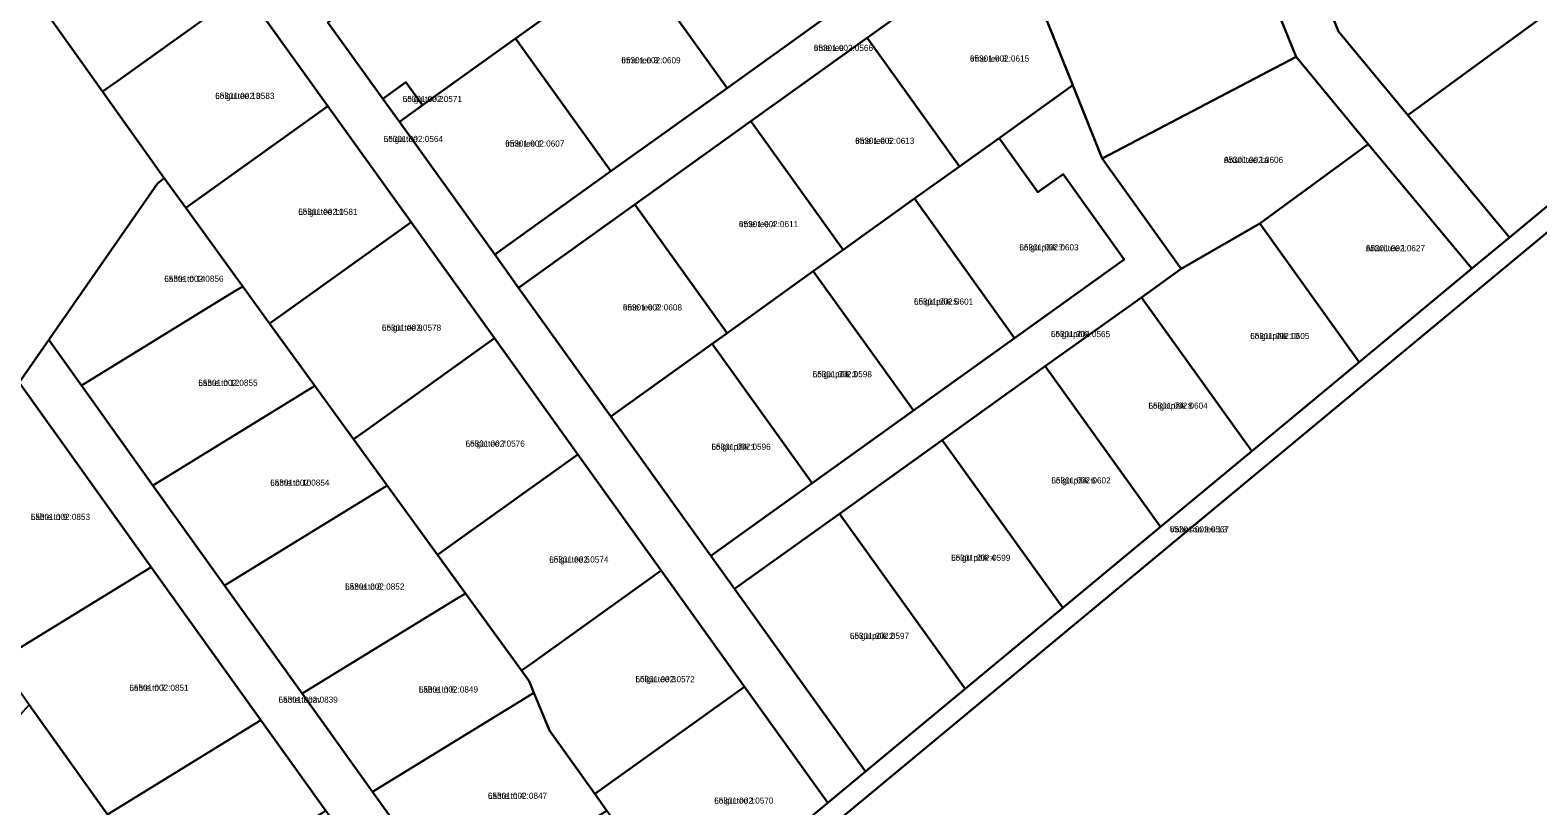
# Model space of a CAD drawing. Extents: x 543236 to 563717, y 6566033 to 6588992.
# Drawn here: x 547510.5 to 547879.6, y 6584286.1 to 6584476.1 of the extents above; entities that cross this region are included whole.
import ezdxf

# ---------------------------------------------------------------- set-up
doc = ezdxf.new("R2010")
doc.units = 0
for name, color, linetype in [('L_AADRESS', 7, 'Continuous'), ('PIIR', 7, 'Continuous'), ('TUNNUS', 7, 'Continuous')]:
    doc.layers.add(name, color=color, linetype=linetype)

msp = doc.modelspace()

# ---------------------------------------------------------------- linework, layer by layer
at = {"layer": 'PIIR'}
for points in [[(547954.94, 6584897.14), (548418, 6584661.07), (548073.21, 6584219.71), (547822.9, 6584045.85), (547791.34, 6584089.91), (547762.23, 6584130.56), (547726.58, 6584180.33), (547703.79, 6584212.15), (547681.42, 6584243.38), (547673.85, 6584253.95), (547904.47, 6584445.32), (547908.07, 6584486.9), (547820.46, 6584606.43), (547748.48, 6584706.18), (547740.64, 6584722.91), (547735.69, 6584759.78), (547742.32, 6584763.93)], [(547796.24, 6584529.04), (547800, 6584519.77), (547750.86, 6584499.7), (547715.36, 6584474.23), (547686.92, 6584453.83), (547658.48, 6584433.43), (547630.04, 6584413.03), (547624.21, 6584421.16), (547652.65, 6584441.56), (547681.09, 6584461.96), (547709.53, 6584482.36), (547737.97, 6584502.76), (547745.99, 6584508.51), (547769.91, 6584518.28)], [(547878.99, 6584526.57), (547902.04, 6584495.12), (547900.01, 6584493.63), (547847.76, 6584455.33), (547830.78, 6584475.79), (547825.95, 6584487.7), (547876.96, 6584525.09)], [(547820.36, 6584469.56), (547772.89, 6584444.67), (547750.86, 6584499.7), (547800, 6584519.77)], [(547542.55, 6584514.42), (547562.95, 6584485.98), (547531.95, 6584463.74), (547528.23, 6584461.08), (547507.95, 6584489.6), (547510.92, 6584491.73)], [(547686.22, 6584514.86), (547709.53, 6584482.36), (547681.09, 6584461.96), (547657.78, 6584494.46)], [(547632.16, 6584513.01), (547649.65, 6584488.63), (547629.34, 6584474.06), (547606.58, 6584457.74), (547602.5, 6584463.43), (547596.82, 6584459.35), (547583.41, 6584478.04)], [(547750.86, 6584499.7), (547765.71, 6584462.62), (547747.69, 6584449.71), (547737.96, 6584442.73), (547715.36, 6584474.23)], [(547657.78, 6584494.46), (547681.09, 6584461.96), (547652.65, 6584441.56), (547629.34, 6584474.06), (547649.65, 6584488.63)], [(547902.04, 6584495.12), (547908.07, 6584486.9), (547905.08, 6584452.32), (547872.61, 6584425.38), (547847.76, 6584455.33), (547900.01, 6584493.63)], [(547562.95, 6584485.98), (547583.35, 6584457.54), (547551.49, 6584434.69), (547548.58, 6584432.6), (547543.32, 6584439.85), (547528.23, 6584461.08), (547531.95, 6584463.74)], [(547629.34, 6584474.06), (547652.65, 6584441.56), (547624.21, 6584421.16), (547600.9, 6584453.66), (547606.58, 6584457.74)], [(547715.36, 6584474.23), (547737.96, 6584442.73), (547726.99, 6584434.86), (547709.52, 6584422.33), (547686.92, 6584453.83)], [(547820.36, 6584469.56), (547838.06, 6584448.23), (547811.47, 6584428.74), (547792.25, 6584417.68), (547772.89, 6584444.67)], [(547602.5, 6584463.43), (547606.58, 6584457.74), (547600.9, 6584453.66), (547596.82, 6584459.35)], [(547765.71, 6584462.62), (547772.89, 6584444.67), (547792.25, 6584417.68), (547782.5, 6584410.68), (547758.97, 6584393.81), (547733.78, 6584375.74), (547708.59, 6584357.67), (547682.95, 6584339.27), (547677.12, 6584347.4), (547701.9, 6584365.18), (547726.69, 6584382.95), (547751.47, 6584400.73), (547778.3, 6584419.98), (547763.33, 6584440.83), (547757.2, 6584436.44), (547747.69, 6584449.71)], [(547583.35, 6584457.54), (547603.75, 6584429.1), (547571.86, 6584406.23), (547569.13, 6584404.27), (547548.58, 6584432.6), (547551.49, 6584434.69)], [(547686.92, 6584453.83), (547709.52, 6584422.33), (547702.21, 6584417.08), (547681.08, 6584401.93), (547658.48, 6584433.43)], [(547905.08, 6584452.32), (547904.47, 6584445.32), (547673.85, 6584253.95), (547670.93, 6584258.03), (547705.74, 6584286.91), (547715, 6584294.59), (547739.35, 6584314.8), (547763.26, 6584334.64), (547787.18, 6584354.49), (547809.52, 6584373.02), (547835.79, 6584394.83), (547863.38, 6584417.72), (547872.61, 6584425.38)], [(547747.69, 6584449.71), (547757.2, 6584436.44), (547763.33, 6584440.83), (547778.3, 6584419.98), (547751.47, 6584400.73), (547726.99, 6584434.86), (547737.96, 6584442.73)], [(547838.06, 6584448.23), (547863.38, 6584417.72), (547835.79, 6584394.83), (547811.47, 6584428.74)], [(547515.08, 6584400.26), (547541.71, 6584438.59), (547543.32, 6584439.85), (547548.58, 6584432.6), (547562.53, 6584413.37), (547560.47, 6584412.11), (547523.04, 6584389.14)], [(547658.48, 6584433.43), (547681.08, 6584401.93), (547677.42, 6584399.3), (547652.64, 6584381.53), (547630.04, 6584413.03)], [(547726.99, 6584434.86), (547751.47, 6584400.73), (547726.69, 6584382.95), (547702.21, 6584417.08), (547709.52, 6584422.33)], [(547603.75, 6584429.1), (547624.15, 6584400.66), (547592.59, 6584378.02), (547589.68, 6584375.94), (547569.13, 6584404.27), (547571.86, 6584406.23)], [(547811.47, 6584428.74), (547835.79, 6584394.83), (547809.52, 6584373.02), (547782.5, 6584410.68), (547792.25, 6584417.68)], [(547702.21, 6584417.08), (547726.69, 6584382.95), (547701.9, 6584365.18), (547677.42, 6584399.3), (547681.08, 6584401.93)], [(547523.04, 6584389.14), (547560.47, 6584412.11), (547562.53, 6584413.37), (547569.13, 6584404.27), (547580.22, 6584388.98), (547578.1, 6584387.68), (547540.57, 6584364.65)], [(547782.5, 6584410.68), (547809.52, 6584373.02), (547787.18, 6584354.49), (547758.97, 6584393.81)], [(547507.82, 6584389.8), (547515.08, 6584400.26), (547523.04, 6584389.14), (547540.57, 6584364.65), (547558.1, 6584340.14), (547577.06, 6584313.65), (547594.28, 6584289.6), (547614.1, 6584261.88), (547631.26, 6584237.89), (547634.77, 6584233), (547619.36, 6584223.87), (547620.93, 6584231.75), (547598.78, 6584262.7), (547582.89, 6584284.91), (547567, 6584307.11), (547540.14, 6584344.63)], [(547624.15, 6584400.66), (547644.55, 6584372.22), (547613.4, 6584349.88), (547610.23, 6584347.61), (547589.68, 6584375.94), (547592.59, 6584378.02)], [(547677.42, 6584399.3), (547701.9, 6584365.18), (547677.12, 6584347.4), (547652.64, 6584381.53)], [(547758.97, 6584393.81), (547787.18, 6584354.49), (547763.26, 6584334.64), (547733.78, 6584375.74)], [(547481.19, 6584351.47), (547507.82, 6584389.8), (547540.14, 6584344.63), (547502.58, 6584321.58)], [(547540.57, 6584364.65), (547578.1, 6584387.68), (547580.22, 6584388.98), (547589.68, 6584375.94), (547597.92, 6584364.58), (547595.56, 6584363.13), (547558.1, 6584340.14)], [(547733.78, 6584375.74), (547763.26, 6584334.64), (547739.35, 6584314.8), (547708.59, 6584357.67)], [(547644.55, 6584372.22), (547664.95, 6584343.78), (547633.13, 6584320.95), (547630.78, 6584319.27), (547610.23, 6584347.61), (547613.4, 6584349.88)], [(547558.1, 6584340.14), (547595.56, 6584363.13), (547597.92, 6584364.58), (547610.23, 6584347.61), (547617.06, 6584338.19), (547614.85, 6584336.83), (547577.06, 6584313.65)], [(547708.59, 6584357.67), (547739.35, 6584314.8), (547715, 6584294.59), (547682.95, 6584339.27)], [(547502.58, 6584321.58), (547540.14, 6584344.63), (547567, 6584307.11), (547529.44, 6584284.06), (547510.24, 6584310.89)], [(547664.95, 6584343.78), (547685.35, 6584315.34), (547648.73, 6584289.07), (547646.65, 6584291.98), (547637.64, 6584304.57), (547632.66, 6584316.69), (547630.78, 6584319.27), (547633.13, 6584320.95)], [(547577.06, 6584313.65), (547614.85, 6584336.83), (547617.06, 6584338.19), (547630.78, 6584319.27), (547632.66, 6584316.69), (547633.82, 6584313.86), (547630.6, 6584311.89), (547594.28, 6584289.6)], [(547685.35, 6584315.34), (547705.74, 6584286.91), (547670.93, 6584258.03), (547651.69, 6584284.94), (547648.73, 6584289.07)], [(547486.09, 6584283.92), (547510.24, 6584310.89), (547529.44, 6584284.06), (547535.06, 6584276.21), (547509.05, 6584251.84)], [(547594.28, 6584289.6), (547630.6, 6584311.89), (547633.82, 6584313.86), (547637.64, 6584304.57), (547646.65, 6584291.98), (547648.73, 6584289.07), (547651.69, 6584284.94), (547614.1, 6584261.88)], [(547529.44, 6584284.06), (547567, 6584307.11), (547582.89, 6584284.91), (547545.32, 6584261.86), (547535.06, 6584276.21)]]:
    msp.add_lwpolyline(points, close=True, dxfattribs=at)
for points in [[(547214.58, 6584431.86), (547258.17, 6584485.37), (547313.31, 6584553.23), (547362.18, 6584612.06), (547381.94, 6584637.66), (547389.25, 6584646.78), (547402.56, 6584639.68), (547426.83, 6584603.49), (547445.02, 6584578.4), (547464.22, 6584551.11), (547487.67, 6584518.13), (547507.95, 6584489.6), (547528.23, 6584461.08), (547543.32, 6584439.85), (547541.71, 6584438.59), (547515.08, 6584400.26), (547507.82, 6584389.8), (547481.19, 6584351.47), (547459.79, 6584320.66), (547431.46, 6584279.88)], [(547825.95, 6584487.7), (547830.78, 6584475.79), (547847.76, 6584455.33), (547872.61, 6584425.38), (547863.38, 6584417.72), (547838.06, 6584448.23), (547820.36, 6584469.56), (547800, 6584519.77)], [(547583.41, 6584478.04), (547596.82, 6584459.35), (547600.9, 6584453.66), (547624.21, 6584421.16), (547630.04, 6584413.03), (547652.64, 6584381.53), (547677.12, 6584347.4), (547682.95, 6584339.27), (547715, 6584294.59), (547705.74, 6584286.91), (547685.35, 6584315.34), (547664.95, 6584343.78), (547644.55, 6584372.22), (547624.15, 6584400.66), (547603.75, 6584429.1), (547583.35, 6584457.54), (547562.95, 6584485.98)]]:
    msp.add_lwpolyline(points, dxfattribs=at)

# ---------------------------------------------------------------- texts
at = {"layer": 'L_AADRESS'}
for s, p in [('Irme tee 3', (547655.22, 6584468.01)), ('Irme tee', (547702.32, 6584471.04)), ('Irme tee 8', (547740.54, 6584468.43)), ('Loigu tee 13', (547555.8, 6584459.29)), ('Loigu tee 2', (547601.7, 6584458.54)), ('Loigu tee', (547597.05, 6584448.74)), ('Irme tee 1', (547626.77, 6584447.61)), ('Irme tee 6', (547712.44, 6584448.28)), ('Arturi tee 1a', (547802.71, 6584443.62)), ('Loigu tee 11', (547576.13, 6584430.9)), ('Irme tee 4', (547684, 6584427.88)), ('Loigu põik 7', (547752.64, 6584422.18)), ('Arturi tee 1', (547837.43, 6584421.98)), ('Lähte tn 14', (547543.34, 6584414.5)), ('Loigu põik 5', (547726.84, 6584408.91)), ('Irme tee 2', (547655.56, 6584407.48)), ('Loigu tee 9', (547596.61, 6584402.52)), ('Loigu põik', (547760.35, 6584400.95)), ('Loigu põik 10', (547809.14, 6584400.47)), ('Loigu põik 3', (547702.05, 6584391.13)), ('Lähte tn 12', (547551.67, 6584389.01)), ('Loigu põik 8', (547784.25, 6584383.41)), ('Loigu tee 7', (547617.08, 6584374.13)), ('Loigu põik 1', (547677.27, 6584373.35)), ('Lähte tn 10', (547569.26, 6584364.56)), ('Loigu põik 6', (547760.48, 6584365.11)), ('Lähte tn 9', (547510.66, 6584356.18)), ('Vahesoo tee L3', (547789.46, 6584353.13)), ('Loigu põik 4', (547735.93, 6584346.16)), ('Loigu tee 5', (547637.56, 6584345.74)), ('Lähte tn 8', (547587.61, 6584339.11)), ('Loigu põik 2', (547711.15, 6584327.03)), ('Loigu tee 3', (547658.67, 6584316.43)), ('Lähte tn 7', (547534.79, 6584314.34)), ('Lähte tn 6', (547605.63, 6584313.9)), ('Lähte tänav', (547571.3, 6584311.41)), ('Lähte tn 4', (547622.55, 6584287.87)), ('Loigu tee 1', (547677.95, 6584286.69))]:
    msp.add_text(s, height=1.5, dxfattribs=at).set_placement(p)
at = {"layer": 'TUNNUS'}
for s, p in [('65301:002:0609', (547655.22, 6584468.01)), ('65301:002:0566', (547702.32, 6584471.04)), ('65301:002:0615', (547740.54, 6584468.43)), ('65301:002:0583', (547555.8, 6584459.29)), ('65301:002:0571', (547601.7, 6584458.54)), ('65301:002:0564', (547597.05, 6584448.74)), ('65301:002:0607', (547626.77, 6584447.61)), ('65301:002:0613', (547712.44, 6584448.28)), ('65301:002:0606', (547802.71, 6584443.62)), ('65301:002:0581', (547576.13, 6584430.9)), ('65301:002:0611', (547684, 6584427.88)), ('65301:002:0603', (547752.64, 6584422.18)), ('65301:002:0627', (547837.43, 6584421.98)), ('65301:002:0856', (547543.34, 6584414.5)), ('65301:002:0601', (547726.84, 6584408.91)), ('65301:002:0608', (547655.56, 6584407.48)), ('65301:002:0578', (547596.61, 6584402.52)), ('65301:002:0565', (547760.35, 6584400.95)), ('65301:002:0605', (547809.14, 6584400.47)), ('65301:002:0598', (547702.05, 6584391.13)), ('65301:002:0855', (547551.67, 6584389.01)), ('65301:002:0604', (547784.25, 6584383.41)), ('65301:002:0576', (547617.08, 6584374.13)), ('65301:002:0596', (547677.27, 6584373.35)), ('65301:002:0854', (547569.26, 6584364.56)), ('65301:002:0602', (547760.48, 6584365.11)), ('65301:002:0853', (547510.66, 6584356.18)), ('65301:002:0567', (547789.46, 6584353.13)), ('65301:002:0599', (547735.93, 6584346.16)), ('65301:002:0574', (547637.56, 6584345.74)), ('65301:002:0852', (547587.61, 6584339.11)), ('65301:002:0597', (547711.15, 6584327.03)), ('65301:002:0851', (547534.79, 6584314.34)), ('65301:002:0849', (547605.63, 6584313.9)), ('65301:002:0572', (547658.67, 6584316.43)), ('65301:002:0839', (547571.3, 6584311.41)), ('65301:002:0847', (547622.55, 6584287.87)), ('65301:002:0570', (547677.95, 6584286.69))]:
    msp.add_text(s, height=1.5, dxfattribs=at).set_placement(p)

doc.saveas('drawing.dxf')
